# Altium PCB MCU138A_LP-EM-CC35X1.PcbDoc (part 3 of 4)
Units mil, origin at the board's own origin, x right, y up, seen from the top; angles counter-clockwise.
Board outline 2309.44 x 2672.36 mil, 4 copper layers (Top Layer, L02_GND, L03_PWR, Bottom Layer), stack 60 mil thick; 235 components, 167 nets, 678 pads, 887 vias.
Unrouted connection lines stored in the file: 19.
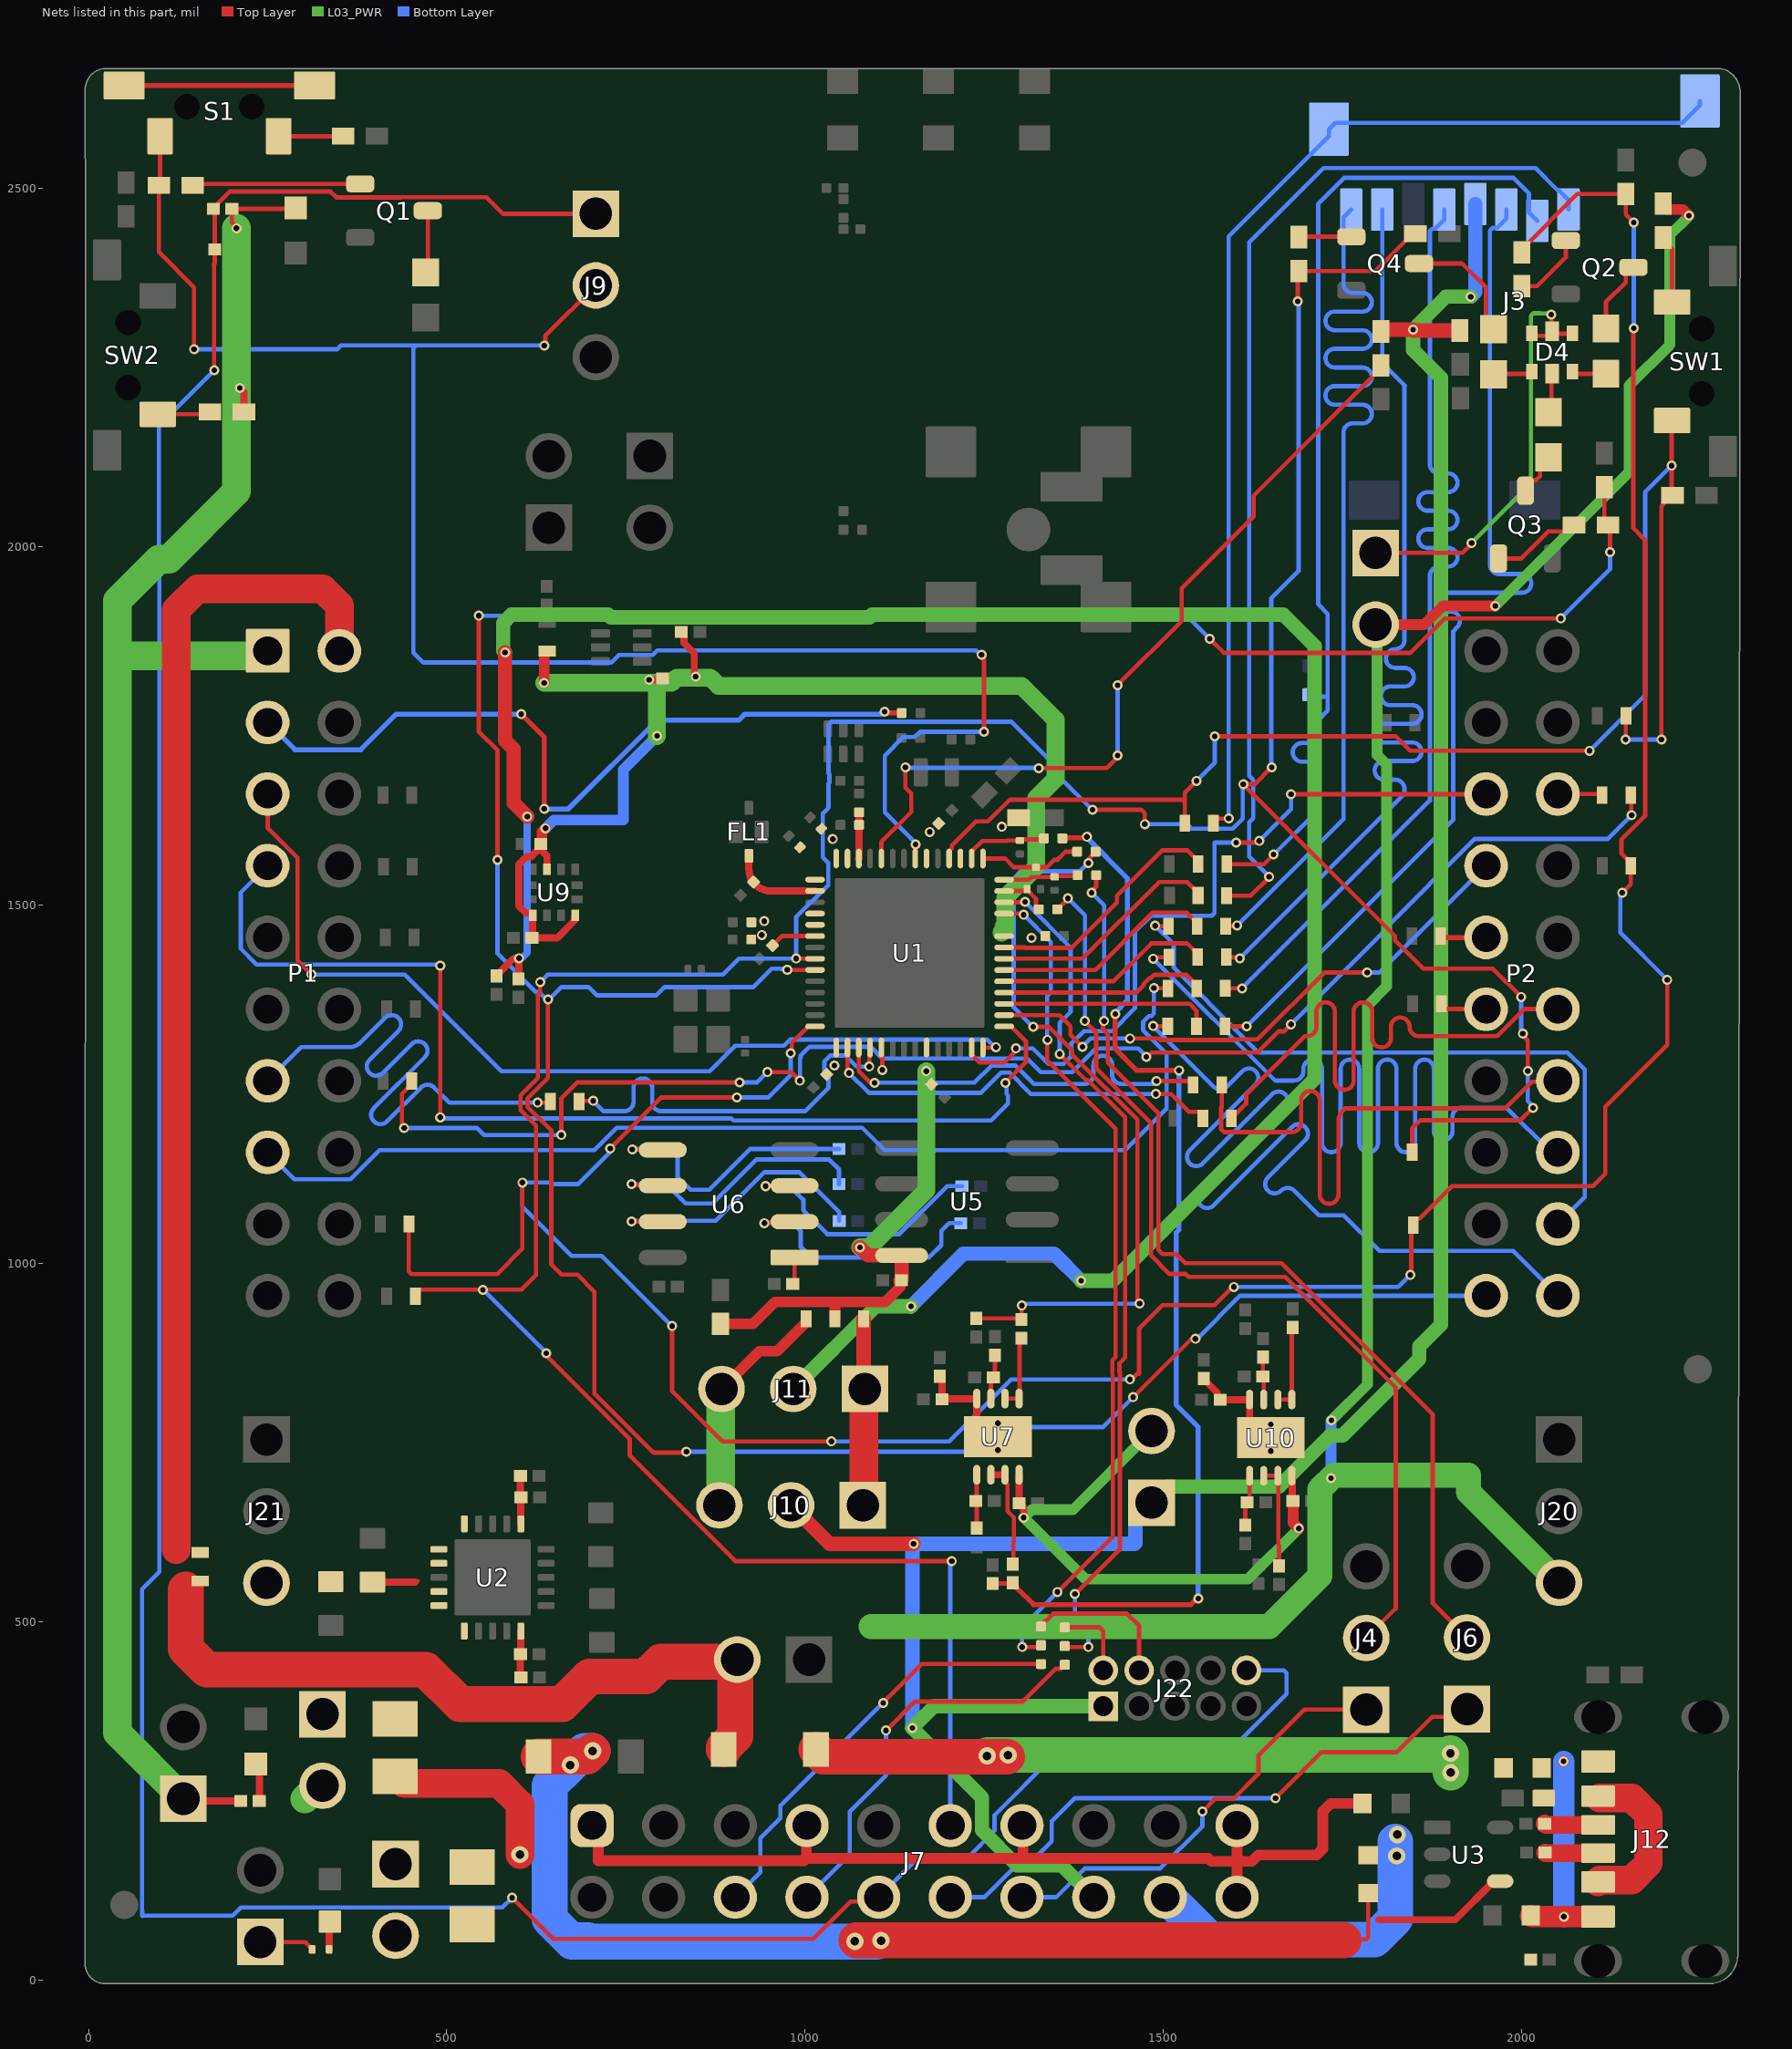
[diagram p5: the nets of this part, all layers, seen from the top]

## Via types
v1: diameter 14, hole 7.87, Top Layer to Bottom Layer, tented both sides, 816 vias
v2: diameter 19.68, hole 7.87, Top Layer to Bottom Layer, tented both sides, 25 vias
v3: diameter 14, hole 8, Top Layer to Bottom Layer, tented both sides, 19 vias
v4: diameter 24, hole 12, Top Layer to Bottom Layer, tented both sides, 14 vias
v5: diameter 19.68, hole 7.87, Top Layer to Bottom Layer, 13 vias

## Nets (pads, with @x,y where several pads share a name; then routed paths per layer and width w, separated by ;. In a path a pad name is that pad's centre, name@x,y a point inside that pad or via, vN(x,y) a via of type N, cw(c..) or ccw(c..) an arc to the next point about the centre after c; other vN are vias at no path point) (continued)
NetD4_1: D4.1 D4.3 D4.5 J19.1 | length 608.6
  Top Layer w6: J19.1@1795.91,1991.39 1916.92,1991.39 1929.83,2004.29 v1(1929.83,2005.24) ; D4.1@2012.62,2294.39 2038.21,2294.39 D4.3@2041.17,2297.34 ; v1(2041.02,2324.1) 2041.17,2323.95 D4.3@2041.17,2297.34 ; D4.5@2069.71,2294.39 2066.76,2297.34 D4.3@2041.17,2297.34
  L03_PWR w6: v1(1929.83,2005.24) 2012.69,2088.1 2012.69,2322.39 2016.21,2325.91 2025.05,2325.91 2025.32,2325.63 2039.49,2325.63 v1(2041.02,2324.1)
NetD4_2: D4.2 R84.2 | length 52.3
  Top Layer w6: R84.2@1960.6,2240.65 1961.19,2241.24 D4.2@2012.62,2241.24
NetD4_4: D4.4 R86.2 | length 52
  Top Layer w6: R86.2@2037.12,2187.93 2041.17,2191.97 D4.4@2041.17,2238.29
NetD4_6: D4.6 R85.2 | length 47.6
  Top Layer w6: D4.6@2069.71,2241.24 2116.87,2241.24 R85.2@2117.21,2241.58
NetD5_1: D5.1 FB3.1 J12.A9 J12.B9 | length 226.3
  Top Layer w40: J12.B9@2106.31,137.01 2108.68,139.39 2152.98,139.39 2176.41,162.82 2176.41,230.88 2152.98,254.31 J12.A9@2108.68,254.31
NetD8_2: D8.2 FB3.2 | length 942.3
  Top Layer w50: D8.2@1015.24,321.96 1025.65,311.55 v4@1281.46,311.55
  L03_PWR w50: v4(1253.88,312.82) 1254.94,313.88 v4(1283.12,313.88) 1283.42,314.18 v4@1898.1,314.18 ; v4(1900.31,316.39) 1900.62,316.08 v4(1900.62,289.57)
NetD9_2: D9.2 R45.1 | length 53.6
  Top Layer w10: D9.2@233.41,301.62 238.37,296.66 R45.1@238.37,250.04
NetD10_2: D10.2 R53.1 | length 39.5
  Top Layer w10: R53.1@335.72,42.82 335.8,42.9 335.8,80.76 D10.2@336.86,81.82
NetFB1_1: FB1.1 J7.18 | length 465.1
  Bottom Layer w50: J7.18@1502.5,115.64 1505.27,115.64 1564.39,56.53 1794.06,56.53 1823.35,85.82 v4@1823.35,193.41
  other v4: 1825.41,173.25 1826.18,202.98
NetFB2_1: FB2.1 J7.1 J7.7 J7.13 J7.19 J7.20 | length 1377.2
  Top Layer w15: J7.1@702.5,215.64 711.29,206.86 711.29,166.46 998.47,166.46 1001.67,169.66 ; J7.7@1002.5,215.64 1001.67,214.82 1001.67,169.66 ; J7.13@1302.5,215.64 1303.99,214.16 1303.99,170.66 ; 1562.5,169.66 1539.77,169.66 1539.63,169.8 1526.38,169.8 1526.24,169.66 1239.77,169.66 1239.63,169.8 1226.38,169.8 1226.24,169.66 1001.67,169.66 ; 1563.21,168.96 1566.52,165.64 1602.5,165.64 ; J7.20@1602.5,115.64 1602.5,165.64 ; J7.19@1602.5,215.64 1602.5,165.64 ; FB2.1@1777.58,246.48 1733.44,246.48 1722.35,235.39 1722.35,183.31 1713.57,174.53 1632.11,174.53 1623.23,165.64 1602.5,165.64
NetFB4_1: FB4.1 J12.A12 J12.B12 R108.2 | length 311.5
  Top Layer w30: FB4.1@2012.22,90.21 2013.77,88.65 v1(2058.52,88.65) 2106.24,88.65 J12.B12@2106.31,88.58
  Bottom Layer w15: v1@2058.15,89.03 v1(2058.52,88.65)
  Bottom Layer w30: v1@2058.15,89.03 v1(2058.15,305.14)
NetJ4_2: J4.2 R96.2 | length 1352.2
  Top Layer w6: R96.2@1351.87,1494.01 1366.69,1508.82 v1(1366.69,1509.37) ; v1(1390.02,1338.25) 1406.09,1322.19 1406.09,1272.09 1482.74,1195.43 1482.74,1010.97 1508.39,985.33 1530.83,985.33 1534.99,981.17 1669.49,981.17 1823.96,826.7 1823.96,518.55 J4.2@1782.8,477.38
  Bottom Layer w6: v1(1366.69,1509.37) 1390.42,1485.64 1390.42,1338.65 v1(1390.02,1338.25)
NetJ6_2: J6.2 R97.2 | length 1374.2
  Top Layer w6: v1(1399.71,1517.26) 1399.71,1519.43 1406.07,1525.78 1406.07,1541.6 R97.2@1406.14,1541.67 ; v1(1417.09,1338.25) 1415.56,1336.72 1415.56,1326.86 1422.07,1320.34 1422.07,1280.41 1492.74,1209.74 1492.74,1018.64 1498.46,1012.93 1517.37,1012.93 1530.09,1000.21 1664.6,1000.21 1875.62,789.18 1875.62,525.8 J6.2@1923.3,478.12
  Bottom Layer w6: v1(1399.71,1517.26) 1399.71,1517.21 1417.09,1499.83 v1(1417.09,1338.25)
NetJ7_6: J7.6 R104.1 | length 599.2
  Top Layer w6: v1(1108.81,386.92) 1162.9,441.02 R104.1@1328.89,441.02
  Bottom Layer w6: J7.6@902.5,115.64 937.28,150.43 937.28,197.93 965.38,226.03 965.38,243.5 v1(1108.81,386.92)
NetJ7_8: J7.8 R105.1 | length 565.8
  Top Layer w6: v1(1112.84,348.26) 1153.24,388.66 1303.76,388.66 1349.64,434.55 1356.97,434.55 1362.24,439.81 R105.1@1362.24,440
  Bottom Layer w6: J7.8@1002.5,115.64 1062.09,175.24 1062.09,235.3 1112.84,286.04 v1(1112.84,348.26)
NetJ12_A5: J12.A5 R48.1 | length 74.1
  Top Layer w25: R48.1@2032.45,177.76 2033.04,177.16 J12.A5@2106.31,177.16
NetJ12_B5: J12.B5 R47.2 | length 75.5
  Top Layer w25: R47.2@2031.62,218.44 2033.52,216.54 J12.B5@2106.31,216.54
NetJ22_2: J22.2 R106.1 | length 110.9
  Top Layer w6: R106.1@1361.99,492.2 1410.87,492.2 1415.87,487.21 J22.2@1415.87,432.24
NetJ22_4: J22.4 R107.1 | length 214.1
  Top Layer w6: R107.1@1328.89,493.48 1328.89,494.26 1345.95,511.32 1449.06,511.32 1465.87,494.51 J22.4@1465.87,432.24
NetQ1_1: Q1.1 R38.2 | length 234.5
  Top Layer w6: R38.2@145.4,2504.22 147.58,2506.39 Q1.1@379.02,2506.39
NetQ1_3: Q1.3 R35.2 | length 87.5
  Top Layer w6: R35.2@470.21,2382.8 473.5,2386.09 Q1.3@473.5,2468.99
NetQ2_1: Q2.1 R87.2 | length 101.8
  Top Layer w6: R87.2@1999.72,2363.68 2021.2,2363.68 2061.21,2403.69 Q2.1@2061.21,2427.43
NetQ2_3: Q2.3 R85.1 | length 102.7
  Top Layer w6: R85.1@2117.21,2304.58 2117.21,2341.18 2144.92,2368.89 2144.92,2381.44 2153.51,2390.03 Q2.3@2155.7,2390.03
NetQ3_1: Q3.1 R88.2 | length 124.5
  Top Layer w6: Q3.1@1967.54,1983.72 1999.22,1983.72 2036.94,2021.43 2063.97,2021.43 R88.2@2072.78,2030.24
NetQ3_3: Q3.3 R86.1 | length 63.8
  Top Layer w6: Q3.3@2004.94,2078.21 2004.94,2084.51 2013.53,2093.1 2019.83,2093.1 2025.32,2098.59 2025.32,2113.14 R86.1@2037.12,2124.94
NetQ4_1: Q4.1 R91.2 | length 73.3
  Top Layer w6: R91.2@1688.91,2432.06 1689.47,2432.61 Q4.1@1761.99,2432.61
NetQ4_3: Q4.3 R84.1 | length 169.9
  Top Layer w6: Q4.3@1856.48,2395.21 1916.53,2395.21 1949.48,2362.27 1949.48,2314.76 R84.1@1960.6,2303.64
NetR8_2: R8.2 SW1.4 | length 95.3
  Top Layer w6: R8.2@2196.85,2431.58 2196.85,2427.65 2209.56,2414.93 SW1.4@2209.56,2341.5
NetR27_2: R27.2 U6.1 | length 37.6
  Top Layer w6: R27.2@982.69,971.7 985.02,974.04 U6.1@985.02,1008.35
NetR36_1: R36.1 S1.3 | length 90.1
  Top Layer w6: S1.3@265.27,2572.79 355.13,2572.79 R36.1@355.29,2572.96
NetR39_1: R39.1 R40.2 U2.16 | length 67.2
  Top Layer w10: R40.2@602.65,703.44 602.65,676 ccw(c605.57,676) R39.1@603.5,673.93 603.25,673.69 U2.16@603.25,636.61
NetR41_1: R41.1 U7.1 U7.2 | length 105.2
  Top Layer w6: U7.2@1278.75,811.42 U7.1@1298.44,811.42 1299.17,812.15 1299.17,893.3 R41.1@1301.51,895.64
NetR41_2: R41.2 R70.2 R95.1 | length 1061.1
  Top Layer w6: R70.2@1238.73,923.25 1299.89,923.25 R41.2@1301.51,921.62 1301.83,921.95 1301.83,940.96 v1(1302.16,941.28) ; v1(1318.07,1330.08) 1339.87,1330.08 1372.74,1297.21 1372.74,1291.29 1463.48,1200.55 1463.48,947.02 v1(1466.64,943.86) ; v1(1394.99,1558.66) 1396.52,1560.19 1396.52,1565.74 R95.1@1405.33,1574.55
  Bottom Layer w6: v1(1302.16,941.28) 1304.73,943.86 v1(1466.64,943.86) ; v1(1318.07,1330.08) 1290.86,1357.29 1290.86,1537.27 1300.79,1547.2 1383.53,1547.2 v1(1394.99,1558.66)
NetR44_1: R44.1 U10.1 U10.2 | length 120.9
  Top Layer w6: U10.2@1659.37,810 U10.1@1679.06,810 ; U10.1@1679.03,810.03 1679.03,909.63 R44.1@1680.17,910.77
NetR49_1: R49.1 R51.2 U2.10 | length 70.9
  Top Layer w10: R51.2@602.28,422.41 ccw(c601.28,423.41) 602.69,423.41 R49.1@602.69,454.64 ccw(c601.33,456) R49.1@603.25,456 ; R49.1@603.25,449.93 U2.10@603.25,487
NetR50_2: R50.2 R68.2 U7.3 | length 62.7
  Top Layer w6: U7.3@1259.07,811.42 1259.07,837.61 1264.71,843.25 R68.2@1264.71,871.82
NetR52_2: R52.2 R69.2 U10.3 | length 59.7
  Top Layer w6: R69.2@1638.56,869.16 1638.56,842.3 R52.2@1638.47,842.21 1639.69,840.99 U10.3@1639.69,810
NetR54_1: R54.1 U1.6 | length 67.3
  Top Layer w6.17: R54.1@952.62,1441.84 967.47,1456.7 U1.6@1013.79,1456.7
NetR56_2: R56.2 U6.6 | length 397.4
  Top Layer w6.17: v1(757.56,1110.58) 758.67,1109.47 800.28,1109.47 U6.6@801.39,1108.35
  Bottom Layer w6.17: v1(757.56,1110.58) 757.73,1110.41 806.27,1110.41 833.02,1083.66 870.39,1083.66 931.74,1145.01 1033.37,1145.01 1047.17,1131.21 R56.2@1047.17,1110.41
NetR57_2: R57.2 U6.5 | length 394.9
  Top Layer w6.17: v1(758.67,1159.19) 759.09,1158.77 800.97,1158.77 U6.5@801.39,1158.35
  Bottom Layer w6.17: v1(758.67,1159.19) 758.99,1159.51 810.7,1159.51 821.82,1148.39 821.82,1120.81 839.91,1102.73 865.98,1102.73 922.77,1159.51 R57.2@1047.17,1159.51
NetR58_2: R58.2 U6.2 | length 381.4
  Top Layer w6.17: v1(943.04,1056.31) 944.06,1057.33 984,1057.33 U6.2@985.02,1058.35
  Bottom Layer w6.17: v1(943.04,1056.31) 982.64,1056.31 993.82,1045.12 993.82,1022.97 1008.45,1008.35 1172.9,1008.35 1190.03,1025.47 1190.03,1045.47 1200.86,1056.31 R58.2@1217.15,1056.31
NetR59_2: R59.2 U6.3 | length 378.9
  Top Layer w6.17: v1(944.65,1107.86) 944.9,1108.11 984.78,1108.11 U6.3@985.02,1108.35
  Bottom Layer w6.17: v1(944.65,1107.86) 978.45,1107.86 997.35,1088.96 997.35,1074.17 1030.71,1040.81 1131.11,1040.81 1198.16,1107.86 R59.2@1218.77,1107.86
NetR60_2: R60.2 U6.7 | length 397.3
  Top Layer w6.17: v1(757.8,1058.67) 757.96,1058.51 801.23,1058.51 U6.7@801.39,1058.35
  Bottom Layer w6.17: v1(757.8,1058.67) 758.57,1059.43 875.25,1059.43 943.29,1127.47 991.77,1127.47 1047.44,1071.8 R60.2@1047.44,1059.43
NetR72_1: R72.1 U7.6 U7.7 | length 150.1
  Top Layer w6: U7.7@1278.75,705.12 1278.75,695.22 1282.29,691.68 1282.29,654.39 1291.01,645.67 1291.01,611.87 1290.37,611.23 1290.37,580.95 R72.1@1289.73,580.31
  Top Layer w10: U7.6@1259.07,705.12 U7.7@1278.75,705.12
NetR72_2: R72.2 R78.2 R98.1 | length 1517.9
  Top Layer w6: R78.2@1261.8,553.32 1288.73,553.32 R72.2@1289.73,554.33
  Top Layer w7: R72.2@1289.73,554.33 1289.73,553.54 1295.39,547.88 1295.39,547.31 1318.62,524.09 1538.23,524.09 1546.46,532.31 v1(1548.35,532.31) ; R98.1@1358.85,1593.09 1359.91,1594.14 1391.91,1594.14 v1(1392.97,1595.2) ; v1(1432.57,1348.21) 1432.57,1299.35 1462.52,1269.41 v1(1521.54,1269.41)
  Bottom Layer w7: v1(1392.97,1595.2) 1392.97,1594.01 1449.4,1537.58 1449.4,1366.93 1432.57,1350.1 v1(1432.57,1348.21) ; v1(1521.54,1269.41) 1521.54,1046.92 1517.4,1042.79 1517.4,802.77 1548.35,771.82 v1(1548.35,532.31)
NetR73_1: R73.1 U10.6 U10.7 | length 146.2
  Top Layer w6: U10.6@1639.69,703.7 U10.7@1659.37,703.7 1660.1,702.98 1660.1,607.54 1660.82,606.82 1661.05,606.6 1661.05,578.19 R73.1@1661.27,577.97
NetR74_2: R74.2 R76.2 U7.5 | length 75.7
  Top Layer w6: R76.2@1239.37,630.66 1239.37,666.82 R74.2@1237.89,668.3 1239.38,669.78 U7.5@1239.38,705.12
NetR75_2: R75.2 R77.2 U10.5 | length 71.2
  Top Layer w6: R77.2@1613.95,634.96 1613.95,664.17 R75.2@1616.54,666.76 1620,670.22 U10.5@1620,703.7
NetR83_2: R83.2 SW2.4 | length 74.3
  Top Layer w6: SW2.4@96.72,2184.8 166.22,2184.8 R83.2@169.63,2188.22
NetS1_1: S1.1 S1.2 | length 265.7
  Top Layer w7: S1.2@49.72,2643.66 S1.1@315.47,2643.66
OP_n: C18.1 R81.2 U10.4 U10.9 | length 201.8
  Top Layer w10: R81.2@1555.93,839.35 1555.93,838.56 1574.95,819.54 1574.95,813.28 1578.22,810.02 C18.1@1579.01,810.02 U10.4@1620,810 1620,767.68 v5(1649.53,738.15) U10.9@1649.53,756.85 v5(1649.53,775.55)
OP_n_1: C17.2 R80.2 U7.4 U7.9 | length 169.4
  Top Layer w10: R80.2@1188.03,842.53 1190.91,839.65 1190.91,814 1191.02,813.89 C17.2@1191.02,810.73 1191.36,811.07 1239.04,811.07 U7.4@1239.38,811.42 U7.9@1239.38,783.81 ; U7.9@1246.22,776.97 v5(1268.91,776.97) U7.9@1268.91,758.27 v5(1268.91,739.57)
P8_GPIO35: J7.11 R21.2 R26.1 R91.1 R93.1 U1.8 | length 5103.3
  Top Layer w6: R26.1@456.16,954.26 456.16,958.76 460.66,963.26 v1@550.38,963.26 ; v1(550.38,963.19) v1@550.38,963.26 ; v1@550.38,964.74 v1@550.38,963.26 ; v1(630.26,1392.44) 630.26,1377.38 627.1,1374.21 627.1,1258.71 602.61,1234.23 602.61,1214.35 624.53,1192.43 624.53,983.55 604.24,963.26 v1@550.38,963.26 ; v1(638.83,874.74) 638.83,871.37 755.22,754.98 755.22,731.81 902.4,584.63 v1(1204.61,584.63) ; v1(987.31,1425.35) 987.45,1425.2 U1.8@1013.79,1425.2 ; v1(1400.75,1633.03) 1469.06,1633.03 1473.77,1628.32 v1(1473.77,1612.97) ; v1(1650.88,1692.35) 1627.17,1668.65 v1(1611.17,1668.61) v1(1611.17,1668.61) 1822.96,1456.82 1822.96,1451.02 1862.57,1411.42 1959.41,1411.42 v1(1999.02,1371.81) ; v1(1687.15,2342.54) 1687.15,2383.05 R91.1@1688.91,2384.81 1795.69,2384.81 1847.51,2436.62 R93.1@1851.45,2436.62 ; R21.2@1846.84,1155.21 1846.84,1188.36 1858.4,1199.92 1998.26,1199.92 v1(2015.47,1217.14) ; v1(2001.21,1320.8) 2001.21,1318.64 2008.24,1311.61 v1(2008.24,1268.38)
  Bottom Layer w6: v1(550.38,963.19) v1(638.83,874.74) ; v1(630.26,1392.44) 640.78,1402.96 885.06,1402.96 907.46,1425.35 v1(987.31,1425.35) 987.31,1483.23 1032.07,1527.99 1032.07,1559.19 1024.54,1566.71 1024.54,1627.89 1032.63,1635.98 1032.63,1669.59 1033.88,1670.84 1033.88,1682.44 1032.63,1683.69 1032.63,1752.29 1036.15,1755.81 1287.95,1755.81 1356.35,1687.41 1356.35,1677.43 v1(1400.75,1633.03) ; J7.11@1202.51,215.65 1202.51,582.53 v1(1204.61,584.63) ; v1(1473.77,1612.97) 1533.24,1612.97 1539.42,1606.79 1596.72,1606.79 1610.6,1620.67 1610.6,1668.04 v1(1611.17,1668.61) ; v1(1650.88,1692.35) 1650.19,1693.03 1650.19,1928.11 1688.33,1966.24 1688.33,2341.36 v1(1687.15,2342.54) ; v1(1999.02,1371.81) 1999.02,1322.99 v1(2001.21,1320.8) ; v1(2008.24,1268.38) 2008.24,1226.54 2015.47,1219.31 v1(2015.47,1217.14)
P9_GPIO34: P2.31 R88.1 R92.1 U1.9 | length 4728.6
  Top Layer w6: v1(544.54,1903.82) 544.54,1742.32 570.72,1716.15 v1(570.72,1563.21) ; v1(641.1,1368.41) 641.1,1258.57 634.53,1252.01 612.61,1230.09 612.61,1218.49 645.78,1185.32 645.78,998.5 659.93,984.34 682.09,984.34 705.88,960.55 705.88,818.51 788.44,735.95 832.85,735.95 v1(834.28,737.38) ; v1(974.97,1409.71) 975.1,1409.58 1013.66,1409.58 U1.9@1013.79,1409.45 ; v1(1457.52,813.35) 1539.22,895.05 1544.19,895.05 v1(1544.46,894.78) ; v1(1564.23,1871.8) 1584.12,1851.9 1844.62,1851.9 1892.65,1899.94 v1(2054.19,1899.94) ; R92.1@2115.15,2083.15 2115.15,2035.11 R88.1@2120.02,2030.24 2122.92,2027.35 v1(2122.92,1992.67)
  Bottom Layer w6: v1(544.54,1903.82) 1532.21,1903.82 v1(1564.23,1871.8) ; v1(570.72,1563.21) 570.72,1432.19 624.46,1378.44 628.91,1378.44 638.93,1368.41 v1(641.1,1368.41) 642.87,1368.41 660.14,1385.69 697.61,1385.69 709.12,1374.18 792.43,1374.18 803.94,1385.69 927.85,1385.69 953.56,1411.4 965.15,1411.4 965.59,1410.96 973.72,1410.96 v1(974.97,1409.71) ; v1(834.28,737.38) 1242.9,737.38 1261.93,756.41 1272.17,756.41 1287.41,771.65 1415.82,771.65 v1(1457.52,813.35) ; v1(1544.46,894.78) 1546.63,894.78 1606.74,954.89 P2.31@1949.99,954.89 ; v1(2054.19,1899.94) 2122.92,1968.67 v1(2122.92,1992.67)
P14_GPIO30: R11.1 R23.1 R24.2 R87.1 R94.1 U1.14 | length 4476.1
  Top Layer w6: R23.1@447.09,1054.98 447.09,988.74 450.61,985.22 570.19,985.22 605.42,1020.46 v1(605.42,1112.86) ; v1(728.12,1160.43) 799.31,1231.62 v1(904.56,1231.62) ; v1(814.24,912.67) 814.24,822.2 884.76,751.68 v1(1036.67,751.68) ; v1(979.64,1293.15) 981.17,1294.68 981.17,1307.94 1003.94,1330.71 U1.14@1013.79,1330.71 ; v1(1453.15,838.12) 1455.31,838.12 1463.21,846.01 1465.74,846.01 1465.74,908.86 1498.57,941.68 1570.86,941.68 1596.35,967.17 v1(1598.26,967.17) ; v1(1844.13,983.82) 1845.66,985.35 1845.66,1050.68 R24.2@1848.54,1053.55 1848.54,1058.05 1853.04,1062.55 1857.54,1062.55 1902.81,1107.83 2099.08,1107.83 2116.2,1124.95 2116.2,1218.47 2202.74,1305.01 v1(2202.74,1395.73) ; R87.1@1999.72,2410.93 1999.72,2414.87 2077.1,2492.25 R94.1@2144.85,2492.25 2144.85,2463.74 v1(2156.21,2452.38) ; v1(2139.93,1517.17) 2152.06,1529.3 R11.1@2152.06,1554.65 2152.06,1559.15 2138.85,1572.36 2138.85,1591.44 2171.93,1624.53 2171.93,2009.44 2155.56,2025.81 2155.56,2304.11 v1(2156.15,2304.69)
  Bottom Layer w6: v1(728.12,1160.43) 728.12,1155.47 683.47,1110.83 646.54,1110.83 644.52,1112.86 v1(605.42,1112.86) 605.42,1079.11 673.94,1010.59 716.26,1010.59 v1(814.24,912.67) v1(814.24,912.67) ; v1(904.56,1231.62) 948.98,1231.62 979.64,1262.28 v1(979.64,1293.15) ; v1(1036.67,751.68) 1200.65,751.68 1287.09,838.12 v1(1453.15,838.12) ; v1(1598.26,967.17) 1827.48,967.17 v1(1844.13,983.82) ; v1(2139.93,1517.17) 2137.14,1514.37 2137.14,1461.33 v1(2202.74,1395.73) ; v1(2156.15,2304.69) 2156.15,2452.31 v1(2156.21,2452.38)
P16_GPIO29: R16.1 R20.1 U1.16 | length 582.4
  Top Layer w6: U1.16@1059.06,1301.19 1059.06,1269.82 1061.02,1267.86 v1(1061.02,1265.69) ; v1(1489.36,1236.4) 1510.41,1236.4 1535.23,1211.58 1550.33,1211.58 1554.73,1207.18 R16.1@1554.73,1202.27
  Bottom Layer w6: v1(1061.02,1265.69) 1088.7,1238.01 1245.51,1238.01 1273.59,1266.1 1285.19,1266.1 1314.89,1236.4 v1(1489.36,1236.4)
P17_GPIO28: R61.1 U1.17 | length 588.1
  Top Layer w6: U1.17@1074.81,1301.19 1074.81,1268.39 1091.46,1251.74 1096.43,1251.74 v1(1096.71,1252.01) ; v1(1490.23,1254.38) 1536.69,1254.38 1541.19,1249.88 R61.1@1541.19,1249.07
  Bottom Layer w6: v1(1096.71,1252.01) 1097.43,1251.3 1098.26,1252.12 1236.09,1252.12 1260.07,1276.1 1293.83,1276.1 1319.41,1250.51 1334.19,1250.51 1389.19,1250.51 ccw(c1389.19,1263.51) 1402.19,1263.51 1402.19,1276.89 cw(c1415.19,1276.89) 1428.19,1276.89 1428.19,1263.51 ccw(c1441.19,1263.51) 1441.19,1250.51 1464.13,1250.51 1486.25,1250.51 1490.12,1254.38 v1(1490.23,1254.38)
P18_GPIO27: R82.2 U1.18 | length 576.4
  Top Layer w6: R82.2@684.5,1225.81 685.57,1226.87 v1(704.1,1226.87) ; v1(1089.47,1274.59) 1089.47,1289.75 1090.56,1290.84 U1.18@1090.56,1301.19 U1.18@1090.92,1300.83
  Bottom Layer w6: v1(704.1,1226.87) 718.57,1212.4 744.48,1212.4 747.48,1212.4 ccw(c747.48,1225.4) 760.48,1225.4 760.48,1245.21 cw(c773.48,1245.21) 786.48,1245.21 786.48,1225.4 ccw(c799.48,1225.4) 799.48,1212.4 878.65,1212.4 999.53,1212.4 1032.64,1245.51 1032.64,1260.75 1026.79,1266.6 1026.79,1281.84 1034.99,1290.04 1056.47,1290.04 1071.92,1274.59 v1(1089.47,1274.59)
P19_GPIO26: R9.1 R17.1 U1.19 | length 2151
  Top Layer w6: v1(440.54,1188.88) 437.46,1191.97 437.46,1236.69 450.89,1250.13 R17.1@450.89,1254.63 ; v1(659.78,1179.23) 659.78,1230.48 682.01,1252.71 v1(908.52,1252.71) ; v1(947.25,1266.98) 980.51,1266.98 v1(992.63,1254.86) ; U1.19@1106.31,1301.19 1106.66,1300.83 1106.66,1286.88 1107.49,1286.05 v1(1107.49,1270.05) v1@1107.97,1270.05 ; v1(1476.09,1288.35) 1477.81,1288.35 1483.6,1294.14 1631.14,1294.14 1660.96,1323.97 1668.54,1323.97 1677.89,1333.32 v1(1677.89,1333.65) ; R9.1@2151.98,1653.58 2152.58,1652.98 2152.58,1626.18 v1(2153.18,1625.58)
  Bottom Layer w6: v1(440.54,1188.88) 542.31,1188.88 551.96,1179.23 v1(659.78,1179.23) ; v1(908.52,1252.71) 932.98,1252.71 v1(947.25,1266.98) ; v1(992.63,1254.86) 992.63,1286.34 993.64,1287.35 993.64,1289.77 1006.22,1302.35 1091.19,1302.35 1107.49,1286.05 ; v1(1107.49,1270.05) 1107.49,1286.05 ; v1(1476.09,1288.35) 1464.55,1299.89 1405.66,1299.89 1372.83,1267.06 1328.7,1267.06 1309.66,1286.1 1107.54,1286.1 1107.49,1286.05 ; v1(1677.89,1333.65) 1806.93,1462.69 1806.93,1464.89 1934.45,1592.41 2120.01,1592.41 v1(2153.18,1625.58)
P31_GPIO15: R28.1 R31.2 U1.31 | length 295.6
  Top Layer w6: U1.31@1277.57,1362.21 1536.55,1362.21 1545.82,1352.95 R31.2@1545.82,1330.85
  Top Layer w10: R28.1@1544.8,1329.83 R31.2@1545.82,1330.85
P32_GPIO14: R19.2 R67.2 U1.32 | length 299.5
  Top Layer w6: U1.32@1277.57,1377.96 1462.38,1377.96 1472.57,1388.15 1472.57,1390.12 1480.77,1398.32 1482.75,1398.32 1487.3,1402.87 1531.8,1402.87 1546.18,1388.49 R67.2@1546.18,1383.99 ; R67.2@1546.18,1383.99 1546.18,1379.49 R67.2@1546.18,1383.99
P33_GPIO13: R22.1 R32.2 U1.33 | length 311.5
  Top Layer w6: U1.33@1277.57,1393.71 1430.07,1393.71 1483,1446.64 1532.74,1446.64 1547.5,1431.88 R32.2@1547.5,1427.38 ; R32.2@1547.5,1427.38 1547.5,1422.88 R32.2@1547.5,1427.38
P34_GPIO12: R25.1 R33.2 U1.34 | length 321.9
  Top Layer w6: U1.34@1277.57,1409.45 1404.83,1409.45 1484.8,1489.42 1532.33,1489.42 1546.91,1474.83 R25.1@1546.91,1470.42 ; R25.1@1546.84,1465.91 R33.2@1546.84,1470.41 R25.1@1546.84,1465.91
P35_GPIO11: R14.2 R29.2 U1.35 | length 334.2
  Top Layer w6: U1.35@1277.57,1425.2 1386.86,1425.2 1493.9,1532.24 1533.21,1532.24 1547.83,1517.62 R29.2@1547.83,1513.12 ; R29.2@1547.83,1513.12 1547.83,1508.62 R29.2@1547.83,1513.12
P36_GPIO10: R30.2 R66.2 U1.36 | length 343.5
  Top Layer w6: U1.36@1277.57,1440.95 1306.35,1440.95 1306.95,1440.35 1371.78,1440.35 1434.78,1503.35 1434.78,1513.28 1497.78,1576.28 1533.57,1576.28 1548.18,1561.67 R30.2@1548.18,1557.17
P41_GPIO6: C15.1 R96.1 U1.41 | length 65.2
  Top Layer w6: U1.41@1277.57,1519.69 C15.1@1307.78,1519.69 ; C15.1@1309.71,1522.27 1309.71,1521.28 1322,1508.99 1322,1497.9 R96.1@1325.89,1494.01
P42_GPIO5: C31.1 R97.1 U1.42 | length 105.2
  Top Layer w6: U1.42@1277.57,1535.44 1312.23,1535.44 1316.18,1539.38 C31.1@1347.92,1539.38 1349.06,1540.53 1379.01,1540.53 R97.1@1380.16,1541.67
P43_GPIO4: C12.1 R95.2 U1.43 | length 145.4
  Top Layer w6: U1.43@1248.04,1564.97 1278.86,1564.97 1291.07,1552.76 C12.1@1322.02,1552.76 1337.01,1552.76 1347.29,1563.04 1351.74,1563.04 1352.3,1563.6 1352.41,1563.6 1363.35,1574.55 R95.2@1379.34,1574.55
P44_GPIO3: C32.1 R98.2 U1.44 | length 118
  Top Layer w6: U1.44@1232.29,1564.97 1232.29,1574.81 1247.05,1589.56 1281.94,1589.56 1282.42,1590.04 C32.1@1299.55,1590.04 1301.07,1591.57 1331.35,1591.57 R98.2@1332.87,1593.09
P46_GPIO2: R34.2 R89.1 R99.1 SW1.3 U1.46 | length 2025.7
  Top Layer w6: U1.46@1200.79,1564.97 1200.79,1575.31 1204.75,1579.27 1204.75,1583.34 1238.06,1616.65 1255.07,1616.65 1285.45,1647.03 1526.15,1647.03 1529.66,1643.52 ; R34.2@1529.66,1614.36 1529.66,1643.52 ; v1(1546.03,1673.36) 1529.66,1656.99 1529.66,1643.52 ; v1(1571.43,1735.48) 1824,1735.48 1844.13,1715.35 v1(2094.53,1715.35) ; v1(2144.75,1730.89) 2145.07,1731.21 R99.1@2145.07,1763.93 ; v1(2194.64,1730.89) 2194.64,2056.23 2197.42,2059.01 2197.42,2062.95 2206.23,2071.76 R89.1@2210.17,2071.76 2208.81,2073.11 v1(2208.81,2113.14) 2208.81,2175.4 SW1.3@2209.56,2176.15
  Bottom Layer w6: v1(1546.03,1673.36) 1571.43,1698.76 v1(1571.43,1735.48) ; v1(2094.53,1715.35) 2171.9,1792.72 2171.9,2076.22 v1(2208.81,2113.14) ; v1(2144.75,1730.89) v1(2194.64,1730.89)
P52_GPIO37: R2.2 R4.1 U1.52 | length 1149.8
  Top Layer w6: U1.52@1106.31,1564.97 1106.31,1588.14 1148.01,1629.85 1148.01,1655.88 1139.83,1664.06 v1(1139.83,1692.25) ; v1(1325.94,1691.09) 1420.71,1691.09 1435.78,1706.16 v1(1435.78,1708.67) ; v1(1435.78,1806.84) 1525.15,1896.2 1525.15,1941.67 1625.81,2042.33 1625.81,2071.38 1803.52,2249.1 R4.1@1803.52,2253.03
  Bottom Layer w6: v1(1139.83,1692.25) 1140.41,1691.67 1325.36,1691.67 v1(1325.94,1691.09) ; v1(1435.78,1708.67) v1(1435.78,1806.84)
PA_LDO_OUT: C29.2 U1.1
RESET: J9.2 R38.1 S1.4 U1.49 | length 2583.2
  Top Layer w6: S1.4@99.92,2572.79 99.92,2505.98 R38.1@98.16,2504.22 98.16,2411.17 147.36,2361.97 v1(147.36,2275.57) ; v1(635.9,2280.88) 637.43,2282.42 637.43,2294.11 J9.2@707.96,2364.64 ; U1.49@1153.55,1564.97 1153.55,1584.4 v1(1153.93,1584.79) ; v1(1246.06,1849.16) 1249.6,1845.63 v1(1249.6,1741.81)
  Bottom Layer w6: v1(147.36,2275.57) 346.85,2275.57 352.17,2280.88 456.86,2280.88 ; v1(635.9,2280.88) 456.86,2280.88 ; v1(1153.93,1584.79) 1153.93,1586.95 1111.05,1629.84 1111.05,1708.61 1136.85,1734.42 1152.59,1734.42 1159.99,1741.81 v1(1249.6,1741.81) ; v1(1246.06,1849.16) 1244.64,1849.16 1238.54,1855.26 793.69,1855.26 787.59,1849.16 739.95,1849.16 729.26,1838.47 467.36,1838.47 453.34,1852.49 453.34,2277.37 456.86,2280.88
RF_A: C11.2 C30.2 U1.54 | length 64.8
  Top Layer w10.25: U1.54@1074.81,1564.97 1074.98,1565.13 1074.98,1611.82 C30.2@1075.14,1611.99 C11.2@1075.15,1629.6
RF_BG: C28.2 FL1.1 U1.2 | length 129.8
  Top Layer w10.25: FL1.1@921.34,1570.33 921.34,1550.69 ccw(c952.34,1550.69) 952.34,1519.69 U1.2@1013.79,1519.69
SDMMC_CD: J3.9 R34.1 | length 1582.4
  Top Layer w6: R34.1@1569.66,1614.36 1569.66,1616.29 1574.16,1620.79 v1(1590.92,1620.79)
  Bottom Layer w6: v1(1590.92,1620.79) 1590.92,2433.04 1730.72,2572.84 J3.9@1730.72,2582.68 1739.54,2591.51 2223.87,2591.51 2248.43,2616.07 J3.9@2248.43,2622.05
SDMMC_CLK: J3.5 R67.1 | length 1458.7
  Top Layer w6: R67.1@1586.18,1383.99 1609.2,1383.99 v1(1609.45,1383.75)
  Bottom Layer w6: v1(1609.45,1383.75) 1871.59,1645.89 1871.59,1930.31 1871.59,1959.31 cw(c1884.59,1959.31) 1884.59,1972.31 1897.18,1972.31 ccw(c1897.18,1985.31) 1897.18,1998.31 1868.37,1998.31 cw(c1868.37,2011.31) 1868.37,2024.31 1897.18,2024.31 ccw(c1897.18,2037.31) 1897.18,2050.31 1868.37,2050.31 cw(c1868.37,2063.31) 1868.37,2076.31 1897.18,2076.31 ccw(c1897.18,2089.31) 1897.18,2102.31 1884.59,2102.31 cw(c1884.59,2115.31) 1871.59,2115.31 1871.59,2151.58 1871.59,2440.43 1875.1,2443.95 1878.99,2443.95 1891.74,2456.7 J3.5@1891.74,2470.48
SDMMC_CMD: J3.3 R31.1 | length 1493.4
  Top Layer w6: R31.1@1585.82,1330.85 1615.77,1330.85 v1(1615.82,1330.8)
  Bottom Layer w6: v1(1615.82,1330.8) 1904.17,1619.16 1904.17,1880.88 1904.17,1882.23 1909.64,1887.69 ccw(c1900.44,1896.88) 1900.44,1909.88 1894.59,1909.88 cw(c1894.59,1922.88) 1894.59,1935.88 2000.13,1935.88 ccw(c2000.13,1948.88) 2000.13,1961.88 1968.46,1961.88 cw(c1968.46,1974.88) 1955.46,1974.88 1955.46,2040.14 1955.46,2441.44 1958.97,2444.96 1965.61,2444.96 1978.35,2457.71 J3.3@1978.35,2470.48
SDMMC_D0: J3.7 R32.1 | length 1488.7
  Top Layer w6: R32.1@1587.5,1427.38 1604.83,1427.38 v1(1606.45,1425.76)
  Bottom Layer w6: v1(1606.45,1425.76) 1836.14,1655.44 1836.14,1659.01 1836.14,1662.01 ccw(c1823.14,1662.01) 1823.14,1675.01 1807.48,1675.01 cw(c1807.48,1688.01) 1807.48,1701.01 1846.95,1701.01 ccw(c1846.95,1714.01) 1846.95,1727.01 1807.48,1727.01 cw(c1807.48,1740.01) 1807.48,1753.01 1846.95,1753.01 ccw(c1846.95,1766.01) 1846.95,1779.01 1816.26,1779.01 cw(c1816.26,1792.01) 1816.26,1805.01 1836.14,1805.01 ccw(c1836.14,1818.01) 1836.14,1831.01 1823.14,1831.01 cw(c1823.14,1844.01) 1823.14,1857.01 ccw(c1823.14,1870.01) 1836.14,1870.01 1836.14,1967.32 1836.14,2224.28 ; 1805.12,2255.3 J3.7@1805.12,2470.48 ; 1805.85,2255.42 1836.86,2224.41
SDMMC_D1: J3.8 R33.1 | length 1459.5
  Top Layer w6: R33.1@1586.84,1470.41 1601.41,1470.41 v1(1602.74,1471.74)
  Bottom Layer w6: v1(1602.74,1471.74) 1750.96,1619.96 1750.96,2130.18 1750.96,2159.18 cw(c1763.96,2159.18) 1763.96,2172.18 1777.59,2172.18 ccw(c1777.59,2185.18) 1777.59,2198.18 1738.85,2198.18 cw(c1738.85,2211.18) 1738.85,2224.18 1777.59,2224.18 ccw(c1777.59,2237.18) 1777.59,2250.18 1738.85,2250.18 cw(c1738.85,2263.18) 1738.85,2276.18 1777.59,2276.18 ccw(c1777.59,2289.18) 1777.59,2302.18 1738.85,2302.18 cw(c1738.85,2315.18) 1738.85,2328.18 1777.59,2328.18 ccw(c1777.59,2341.18) 1777.59,2354.18 1763.96,2354.18 cw(c1763.96,2367.18) 1750.96,2367.18 1750.96,2395.98 1750.96,2459.62 J3.8@1761.82,2470.48
SDMMC_D2: J3.1 R29.1 | length 1492.9
  Top Layer w6: R29.1@1587.83,1513.12 1621.62,1513.12 1647.31,1538.81 v1(1647.31,1539.68)
  Bottom Layer w6: v1(1647.31,1539.68) 1619.44,1567.55 1619.44,1615.37 1625.17,1621.1 1625.17,1674.41 1619.44,1680.14 1619.44,2424.84 1723.02,2528.42 2018.92,2528.42 2050.33,2497 2052.22,2497 2064.97,2484.26 J3.1@2064.97,2470.48
SDMMC_D3: J3.2 R30.1 R65.2 | length 1452.2
  Top Layer w6: R30.1@1588.18,1557.17 1640.11,1557.17 v1(1653.62,1570.68)
  Bottom Layer w6: v1(1653.62,1570.68) 1715.85,1632.91 1715.85,1684.16 1715.85,1687.16 ccw(c1702.85,1687.16) 1702.85,1700.16 1693.23,1700.16 cw(c1693.23,1713.16) 1693.23,1726.16 1702.85,1726.16 ccw(c1702.85,1739.16) 1715.85,1739.16 1715.85,1758.24 1728.9,1771.29 1728.9,1776.45 1728.9,1790.95 ; R65.2@1703.53,1793.51 1706.1,1790.95 1728.9,1790.95 ; J3.2@2021.66,2454.73 2009.64,2466.75 2009.64,2493.26 1988.02,2514.88 1752.15,2514.88 1715.85,2478.58 1715.85,1919.56 1728.9,1906.51 1728.9,1790.95
SLOW_CLK_IN: P1.2 R5.2 | length 1091.2
  Top Layer w7: v1(603.77,1766.38) 635.93,1734.21 v1(635.93,1634.13) ; v1(1110.61,1769.81) 1112.3,1768.12 R5.2@1134.66,1768.12
  Bottom Layer w7: P1.2@249.99,1754.89 288,1716.88 379.93,1716.88 429.42,1766.38 v1(603.77,1766.38) ; v1(635.93,1634.13) 669.57,1634.13 793.2,1757.76 907.04,1757.76 915.59,1766.31 1105.22,1766.31 1108.72,1769.81 v1(1110.61,1769.81)
SPI0_CLK: P1.7 R82.1 | length 836.9
  Top Layer w6: v1(626.61,1224.29) 642.99,1224.29 R82.1@644.5,1225.81
  Bottom Layer w6: P1.7@249.99,1254.89 296.85,1301.76 359.61,1301.76 363.85,1301.76 ccw(c363.85,1323.95) 379.52,1308.23 414.04,1342.75 cw(c423.23,1333.56) 432.42,1342.75 cw(c423.23,1333.56) 432.42,1324.36 392.19,1284.13 ccw(c401.38,1274.94) 392.19,1265.74 ccw(c401.38,1274.94) 410.57,1265.74 450.8,1305.98 cw(c460,1296.79) 469.19,1305.98 cw(c460,1296.79) 469.19,1287.59 398.18,1216.58 ccw(c407.37,1207.39) 398.18,1198.2 ccw(c407.37,1207.39) 416.56,1198.2 463.85,1245.49 cw(c473.04,1236.29) 482.24,1245.49 503.44,1224.29 540.48,1224.29 v1(626.61,1224.29) v1@626,1224.9
SPI0_CS: P2.18 R9.2 | length 62.5
  Top Layer w6: P2.18@2049.99,1654.89 2110.66,1654.89 R9.2@2111.98,1653.58
SPI0_PICO: P2.15 R16.2 | length 880.6
  Top Layer w6: R16.2@1594.73,1202.27 1615.2,1222.74 1615.2,1235.11 1697.22,1317.13 1700.22,1317.13 ccw(c1700.22,1330.13) 1713.22,1330.13 1713.22,1351.29 cw(c1726.22,1351.29) 1739.22,1351.29 1739.22,1255.27 ccw(c1752.22,1255.27) 1765.22,1255.27 1765.22,1351.29 cw(c1778.22,1351.29) 1791.22,1351.29 1791.22,1314.4 ccw(c1804.22,1314.4) 1817.22,1314.4 1817.22,1330.13 cw(c1830.22,1330.13) 1843.22,1330.13 ccw(c1856.22,1330.13) 1856.22,1317.13 1905.07,1317.13 1965.27,1317.13 2003.04,1354.89 P2.15@2049.99,1354.89
SPI0_POCI: P2.14 R61.2 | length 865.5
  Top Layer w6: R61.2@1581.19,1249.07 1581.19,1218.13 1580.23,1217.17 1580.23,1187.37 1584.33,1183.27 1646.47,1183.27 1678.96,1183.27 ccw(c1678.96,1196.27) 1691.96,1196.27 1691.96,1227.62 cw(c1704.96,1227.62) 1717.96,1227.62 1717.96,1096.27 ccw(c1730.96,1096.27) 1743.96,1096.27 1743.96,1197.67 cw(c1766.15,1197.67) 1750.46,1213.37 1753.46,1216.37 1976.86,1216.37 2013.99,1253.5 2048.59,1253.5 P2.14@2049.99,1254.89
  Bottom Layer w6: P2.14@2049.99,1252.23 P2.14@2049.99,1254.89
SPI1_CLK: P1.8 R19.1 | length 1546.6
  Top Layer w6: v1(1486.57,1384.32) 1487.02,1383.87 R19.1@1506.25,1383.87
  Bottom Layer w6: P1.8@249.99,1154.89 287.5,1117.38 365.52,1117.38 406.28,1158.14 706.03,1158.14 737.2,1189.31 1079.62,1189.31 1110.79,1158.14 1446.52,1158.14 1504.23,1215.85 1504.23,1292.56 1471.41,1325.38 1471.41,1336.98 1479.61,1345.18 1483.06,1345.18 1486.57,1348.69 v1(1486.57,1384.32)
SPI1_CS: P2.12 R25.2 | length 951.5
  Top Layer w6: v1(1488.35,1471.21) 1489.14,1470.42 R25.2@1506.91,1470.42
  Bottom Layer w6: v1(1488.35,1471.21) 1514.2,1445.36 1514.2,1412.62 1610.02,1316.8 1632.39,1294.43 2063.5,1294.43 2087.5,1270.43 2087.5,1092.41 P2.12@2049.99,1054.89
SPI1_PICO: P2.13 R22.2 | length 1546.6
  Top Layer w6: v1(1485.5,1425.22) 1487.58,1427.31 R22.2@1507.5,1427.31
  Bottom Layer w6: v1(1485.5,1425.22) 1655.58,1255.14 1655.67,1255.14 1679.08,1255.14 1682.08,1255.14 ccw(c1682.08,1268.14) 1695.08,1268.14 1695.08,1271.43 cw(c1708.08,1271.43) 1721.08,1271.43 1721.08,1168.22 ccw(c1734.08,1168.22) 1747.08,1168.22 1747.08,1271.43 cw(c1760.08,1271.43) 1773.08,1271.43 1773.08,1168.14 ccw(c1786.08,1168.14) 1799.08,1168.14 1799.08,1271.43 cw(c1812.08,1271.43) 1825.08,1271.43 1825.08,1168.14 ccw(c1838.08,1168.14) 1851.08,1168.14 1851.08,1271.43 cw(c1864.08,1271.43) 1877.08,1271.43 1877.08,1184.64 ccw(c1890.08,1184.64) 1903.08,1184.64 1903.08,1204.38 cw(c1916.08,1204.38) 1916.08,1217.38 1964.61,1217.38 1978.49,1217.38 2040.97,1154.89 P2.13@2049.99,1154.89
SPI1_POCI: P2.11 R28.2 | length 1546.6
  Top Layer w6: v1(1485.41,1331.18) 1485.78,1330.81 R28.2@1505.98,1330.81
  Bottom Layer w6: v1(1485.41,1331.18) 1567.87,1248.72 1569.99,1246.6 ccw(c1579.19,1255.79) 1588.38,1246.6 1609.99,1268.2 cw(c1619.18,1259.01) 1628.37,1268.2 cw(c1619.18,1259.01) 1628.37,1249.82 1536.43,1157.88 ccw(c1545.62,1148.68) 1536.43,1139.49 ccw(c1545.62,1148.68) 1554.81,1139.49 1651.27,1235.95 cw(c1660.46,1226.76) 1669.65,1235.95 cw(c1660.46,1226.76) 1669.65,1217.57 1551.6,1099.51 ccw(c1560.79,1090.32) 1551.6,1081.12 ccw(c1560.79,1090.32) 1569.98,1081.12 1679.22,1190.36 cw(c1688.41,1181.17) 1697.6,1190.36 cw(c1688.41,1181.17) 1697.6,1171.97 1645.58,1119.95 ccw(c1654.77,1110.76) 1645.58,1101.57 ccw(c1654.77,1110.76) 1663.96,1101.57 cw(c1673.16,1092.37) 1682.35,1101.57 1716.8,1067.12 1751.35,1067.12 1801.09,1017.38 1824.95,1017.38 1987.5,1017.38 P2.11@2049.99,954.89
SWCLK: R104.2 R107.2 U1.39 | length 1189.5
  Top Layer w6: U1.39@1277.57,1488.19 1302.89,1488.19 1304.63,1486.45 v1(1304.86,1486.45) ; v1(1302.7,464.76) 1326.16,464.76 R107.2@1328.89,467.49 ; v1(1338.19,1311.97) 1337.54,1311.31 1337.54,1283.7 1432.94,1188.3 1432.94,869.25 1428.53,864.84 1428.53,844.96 1429.15,844.33 1429.15,618.78 v1(1351.98,541.61)
  Bottom Layer w6: v1(1302.7,464.76) 1302.56,464.9 1302.56,492.18 v1(1351.98,541.61) ; v1(1304.86,1486.45) 1342.76,1448.55 1342.76,1378.33 1337.54,1373.11 1337.54,1312.62 v1(1338.19,1311.97)
SWDIO: R105.2 R106.2 U1.40 | length 1211.7
  Top Layer w6: U1.40@1277.57,1503.94 1305.94,1503.94 v1(1306.55,1504.55) ; v1(1355.02,1292.27) 1391.51,1255.78 1394.11,1255.78 1446.26,1203.64 1446.26,868.42 1438.53,860.7 1438.53,849.1 1439.15,848.48 1439.15,601.34 v1(1376.39,538.59) ; R105.2@1362.24,465.98 1363.47,464.76 v1(1395.1,464.76)
  Bottom Layer w6: v1(1306.55,1504.55) 1370.35,1440.75 1370.35,1350.9 1355.02,1335.57 v1(1355.02,1292.27) ; v1(1376.39,538.59) 1376.39,504.48 1395.1,485.77 v1(1395.1,464.76)
UART0_CTS: P2.38 U1.27 | length 1053.1
  Top Layer w6: U1.27@1232.29,1301.19 1232.29,1291.34 1243.23,1280.41 1278.11,1280.41 1293.95,1296.24 v1(1293.95,1300.1) ; v1(1601.17,1587.2) 1630.41,1587.2 1632.69,1589.48 v1(1633.44,1589.48) ; v1(1677.86,1654.63) 1677.99,1654.76 1949.86,1654.76 P2.38@1949.99,1654.89
  Bottom Layer w6: v1@1293.95,1297.5 v1(1293.95,1300.1) 1317.55,1300.1 1339.38,1278.27 1360.82,1278.27 1370.88,1288.33 1370.88,1306.3 1388.84,1324.25 1428.42,1324.25 1460.05,1355.89 1460.05,1462.71 1482.55,1485.21 1567.5,1485.21 1571.01,1488.72 1571.01,1587.2 v1(1601.17,1587.2) ; v1(1633.44,1589.48) 1677.86,1633.91 v1(1677.86,1654.63)
UART0_RTS: P2.37 U1.30 | length 803.6
  Top Layer w6: U1.30@1277.57,1346.46 1354.78,1346.46 1370,1331.25 1370,1319.1 v1(1386.74,1302.36) ; v1(1453.36,1313.91) 1493.48,1313.91 1495.58,1311.81 1596.18,1311.81 1597.07,1312.7 1631.05,1312.7 1724.23,1405.88 v1(1784.13,1405.88)
  Bottom Layer w6: v1(1386.74,1302.36) 1398.29,1313.91 v1@1452.8,1313.91 ; v1(1784.13,1405.88) 1800.97,1405.88 P2.37@1949.99,1554.89
UART0_RX: P1.3 U1.28 | length 1329.1
  Top Layer w6: P1.3@249.99,1654.89 249.99,1607.94 291.75,1566.18 291.75,1422.69 v1(311.29,1403.15) ; U1.28@1248.04,1301.19 1265.66,1301.19 v1(1266.26,1301.78)
  Bottom Layer w6: v1(311.29,1403.15) 440.96,1403.15 575.9,1268.21 866.67,1268.21 902.38,1303.92 970.61,1303.92 979.04,1312.35 1254.2,1312.35 1264.77,1301.78 v1(1266.26,1301.78)
UART0_TX: P1.4 U1.29 | length 1574.5
  Top Layer w6: v1(490.82,1203.9) v1(490.82,1415.65) ; U1.29@1277.57,1330.71 1287.41,1330.71 1307.95,1310.17 1307.95,1280.66 v1(1279.39,1252.1)
  Bottom Layer w6: P1.4@249.99,1554.89 212.47,1517.38 212.47,1439.36 234.69,1417.15 489.33,1417.15 v1(490.82,1415.65) ; v1(490.82,1203.9) 492.32,1202.4 896.76,1202.4 899.85,1199.31 1259.6,1199.31 1283.01,1222.72 1283.01,1234.32 1280.92,1236.4 1280.92,1250.57 v1(1279.39,1252.1)
UART1_RX: P2.35 R18.1 | length 67.3
  Top Layer w6: R18.1@1887.6,1362.41 1887.6,1359.39 1892.1,1354.89 P2.35@1949.99,1354.89
UART1_RX_XDS: J4.1 J7.14 | length 615.8
  Top Layer w6: v1(1554.25,235.31) 1571.71,252.76 1597.49,252.76 1632.43,287.7 1632.43,313.49 1696.33,377.38 J4.1@1782.8,377.38
  Bottom Layer w6: J7.14@1302.5,115.64 1350.01,115.64 1390.18,155.82 1495.17,155.82 1554.25,214.9 v1(1554.25,235.31)
UART1_TX: P2.36 R13.1 | length 64.2
  Top Layer w7: R13.1@1886.57,1456.82 1888.49,1454.89 P2.36@1949.99,1454.89
UART1_TX_XDS: J6.1 J7.12 | length 846
  Top Layer w6: v1(1656.21,253.86) 1720.46,318.11 1825.56,318.11 1874.88,367.43 1912.61,367.43 J6.1@1923.3,378.12
  Bottom Layer w6: J7.12@1202.5,115.64 1250.01,115.64 1294.24,159.88 1310.27,159.88 1344.13,193.73 1344.13,221.86 1376.13,253.86 v1(1656.21,253.86)
VBAT_CC_1V8: C22.1 C24.1 C25.1 C27.1 J16.1 R63.2 U1.4 U1.5 U1.45 U1.48
  other v3: 939.37,1458.36 942.82,1477.57 1173.85,1602.12 1274.42,1609.22
VCC_BRD_1V8: J10.3 J11.3 J14.1 J16.2 R43.1 R53.2 R63.1 | length 402.1
  Top Layer w6: J14.1@239.78,53.23 302.68,53.23 312.1,43.81 R53.2@312.1,42.82
  Top Layer w15: J11.3@883.3,824.84 935.96,877.5 960.73,877.5 1001.5,918.26 R43.1@1001.5,922.76
  L03_PWR w40: J10.3@880.36,662.51 881.83,663.98 881.83,823.37 J11.3@883.3,824.84
VCC_BRD_3V3: D2.2 J10.1 J11.1 J13.1 J17.2 J19.2 J20.3 P1.1 R8.1 R37.2 R42.2 R45.2 R64.1 R83.1 | length 6621.4
  Top Layer w6: v1(206.51,2444.43) 206.51,2446.6 200.2,2452.9 R37.2@200.2,2471.58 288.01,2471.58 D2.2@289.27,2472.84
  Top Layer w10: J13.1@132.3,253.09 135.36,250.04 R45.2@212.39,250.04 ; v1(211.02,2221.35) 216.87,2215.5 R83.1@216.87,2188.22 ; J11.1@1081.5,826.64 J11.1@1083.3,824.84
  Top Layer w15: J19.2@1795.91,1891.39 1863.59,1891.39 1889.63,1917.42 v1(1962.92,1917.42) ; R8.1@2196.85,2478.83 2196.85,2474.89 2201.16,2470.58 2224.47,2470.58 v1(2233.13,2461.92)
  Top Layer w20: J11.1@1081.5,826.64 R42.2@1081.5,922.76
  Top Layer w35: J20.3@2046.07,560.22 J20.3@2051.8,554.48
  Top Layer w40: R64.1@428.1,284.37 430.71,284.37 440.66,274.42 573.02,274.42 601.91,245.53 v4(601.91,175.23) ; J10.1@1080.36,662.51 1081.83,663.98 1081.83,823.37 J11.1@1083.3,824.84
  L03_PWR w15: v1(1734.43,781.27) 1784.58,831.42 1784.58,1359.87 1811.17,1386.46 1811.17,1696.16 1797.88,1709.45 1797.88,1889.41 J19.2@1795.91,1891.39 ; v1(1962.92,1917.42) 2149.6,2104.1 2149.6,2224.89 2206.5,2281.79 2206.5,2435.29 v1(2233.13,2461.92)
  L03_PWR w35: 1091.98,493.26 1647.5,493.26 1718.09,563.85 1718.09,685.05 1737.69,704.65 1925.39,704.65 1925.39,680.89 J20.3@2051.8,554.48
  L03_PWR w40: J13.1@132.3,253.09 40.42,344.98 40.42,1847.66 ; v1(206.51,2444.43) 206.51,2077.12 112.18,1982.79 98.46,1982.79 40.42,1924.75 40.42,1847.66 ; P1.1@249.99,1854.89 242.75,1847.66 40.42,1847.66 ; J17.2@301.73,253.09 319.75,271.11 J17.2@326.5,271.11
  Bottom Layer w15: v1(1733.58,700.54) 1733.58,780.42 v1(1734.43,781.27)
VCC_BRD_5V: C2.2 C3.2 D8.1 J5.2 J21.3 R46.1 U2.1 U2.2 U2.4 U2.5 U2.6 U2.20 | length 1104.6
  Top Layer w6.17: 455.36,555.13 ccw(c455.36,561.06) 459.55,556.87
  Top Layer w10: C3.2@394.1,555.68 394.65,555.13 455.36,555.13
  Top Layer w50: 135.72,544.78 135.72,462.53 165.01,433.24 470.4,433.24 518.37,385.27 661.06,385.27 699.33,423.54 777.59,423.54 798.34,444.3 J5.2@902.39,444.3 ; D8.1@886.3,321.96 886.3,324.16 902.39,340.25 J5.2@902.39,444.3 ; J5.2@905.26,447.16 J5.2@902.39,444.3
VCC_LP_5V: P1.21 R46.2 | length 1625.3
  Top Layer w40: 122.46,600.99 122.46,1267.01 ; 122.58,1265.42 122.58,1617.79 122.46,1617.67 122.46,1911.78 152.1,1941.42 326.56,1941.42 349.99,1917.99 P1.21@349.99,1854.89
VCC_OPAMP: C13.2 C14.2 J8.2 U7.8 U10.8 | length 814.1
  Top Layer w6: U10.8@1679.06,703.7 U10.8@1679.52,703.24
  Top Layer w10: U7.8@1298.44,705.12 1298.44,665.65 1299.04,665.65 1304.4,660.29 1304.4,657.39 1305.01,656.78 v1(1305.01,645.29) ; C14.2@1679.52,671.61 U10.8@1679.52,703.24
  Top Layer w15: C14.2@1680.49,668.7 1680.94,668.25 1680.94,637.93 v1(1688.68,630.18)
  L03_PWR w15: J8.2@1483.3,766.19 1373.55,656.43 1316.15,656.43 v1(1305.01,645.29) 1390.97,559.33 1617.82,559.33 v1(1688.68,630.18)
VDD_PA: C26.2 J17.1 R64.2 U1.55 U1.56
  other v3: 1038.54,1592.11
VDD_SF_IN: C33.1 C40.1 R42.1 R43.2 R55.2 U1.23 U5.8 | length 696.5
  Top Layer w10: C40.1@1132.65,975.51 1133.42,976.28 C40.1@1134.21,976.28
  Top Layer w15: R55.2@881.8,915.7 927.47,915.7 958.04,946.26 1041.5,946.26 ; R42.1@1041.5,922.76 1041.5,946.26 ; C40.1@1132.65,975.51 1132.65,967.13 1111.79,946.26 1041.5,946.26
  Top Layer w20: v1(1076.55,1022.43) 1087.71,1011.27 1134.24,1011.27 U5.8@1134.49,1011.02 1134.49,977.35 C40.1@1132.65,975.51
  L03_PWR w25: v1(1076.55,1022.43) 1089.31,1022.43 1168.9,1102.02 v3(1168.9,1268.35)
VIO1_IN: C16.1 C34.1 C42.1 J3.4 J7.16 J8.1 J10.2 J22.1 R1.1 R2.1 R62.2 R100.2 R101.2 U1.37 U9.3 U9.7 U9.10 | length 5582.1
  Top Layer w10: 632.03,1576.34 639.66,1568.71 U9.3@639.66,1550.01 ; C16.1@632.03,1577.1 632.03,1585.22 630.46,1585.22 627.19,1581.95 627.19,1577.1 623.32,1573.22 617.61,1567.52 611.17,1567.52 600.34,1556.7 600.34,1498.85 610.28,1488.91 619.46,1488.91 619.97,1488.4 U9.7@619.97,1485.84 619.46,1485.33 619.46,1454.76 C42.1@618.82,1454.12 653.93,1454.12 678.52,1478.7 678.52,1485.33 U9.10@679.03,1485.84 ; v1(782.26,1814.36) 799.28,1814.36 R101.2@801.09,1816.17 ; R100.2@827.02,1881.11 827.81,1881.11 831.08,1877.84 831.08,1865.7 845.13,1851.65 845.13,1820.91 v1(847.13,1818.91)
  Top Layer w15: C16.1@632.03,1585.22 632.8,1585.99 632.8,1602.35 v1(637.72,1607.27) ; v1(635.84,1810.07) 635.84,1854.56 R62.2@640.12,1854.56
  Top Layer w20: J10.2@980.36,662.51 1034.02,608.84 v1(1151.24,608.84) ; R2.1@1803.11,2300.35 1803.11,2301.13 1804.92,2302.94 v1(1848.05,2302.94) 1849.22,2301.77 R1.1@1913.09,2301.77
  L03_PWR w20: J7.16@1402.5,115.64 1357.79,160.36 1295.4,160.36 1246.62,209.13 1246.62,254.67 v1(1149.61,351.68) 1180.16,382.24 J22.1@1415.87,382.24 ; J8.1@1483.3,666.19 1505.78,688.67 1661.17,688.67 1732.28,759.77 1749.91,759.77 1856.87,866.74 1856.87,884.37 1886.87,914.37 1886.87,2235.86 1848.05,2274.67 v1(1848.05,2302.94) 1894.02,2348.91 v1(1928.59,2348.91)
  L03_PWR w25: v1(635.84,1810.07) 793.13,1810.07 ; v1(793.13,1735.92) 793.13,1810.07 ; 1274.08,1461.85 1278.88,1466.65 1278.88,1510.12 1322.55,1553.79 1322.55,1649.4 1349.44,1676.28 1349.44,1758.38 1301.94,1805.87 879.15,1805.87 867.67,1817.34 820.79,1817.34 813.52,1810.07 793.13,1810.07
  Bottom Layer w15: v1(637.72,1607.27) 649.24,1618.79 746.13,1618.79 746.13,1688.92 v1(793.13,1735.92)
  Bottom Layer w20: v1(1149.61,351.68) 1149.61,607.21 v1(1151.24,608.84) 1459.88,608.84 1460.82,609.79 1460.82,643.71 J8.1@1483.3,666.19 ; v1(1928.59,2348.91) 1935.05,2355.36 J3.4@1935.05,2478.35
  other v3: 1315.83,1454.4
VIO2_IN: C35.1 J11.2 R102.2 R103.2 U1.15 | length 3259.5
  Top Layer w10: R102.2@569.59,1401.2 569.59,1401.99 592.74,1425.13 600.06,1425.13 v1@600.52,1425.59 ; R103.2@600.2,1397.11 600.52,1397.42 v1@600.52,1425.59 ; v1(600.83,1425.9) v1@600.52,1425.59
  Top Layer w20: v1(581.21,1852.47) 581.21,1729.7 593.19,1717.72 593.19,1642.44 v1(612.22,1623.41)
  L03_PWR w20: v1(581.21,1852.47) 578.48,1855.2 578.48,1893.55 590.2,1905.27 725.04,1905.27 728.73,1901.58 1089.7,1901.58 1093.39,1905.27 1667.26,1905.27 1710.84,1861.69 1710.84,1257.46 1429.19,975.82 v1(1384.96,975.82) ; J11.2@983.3,824.84 1098.81,940.35 v1(1147.64,940.35)
  Bottom Layer w10: v1(600.83,1425.9) 601.59,1426.66 605.13,1426.66 612.22,1433.76 v1(612.22,1623.41)
  Bottom Layer w20: v1(1147.64,940.35) 1220.9,1013.61 1347.17,1013.61 v1(1384.96,975.82)
  other v3: 1040.79,1276.04
XDS_5V: D1.2 FB1.2 U3.4 | length 1802.7
  Top Layer w6: 1752.76,57.01 1783.25,57.01 1785.48,59.23 FB1.2@1785.48,121.22
  Top Layer w10: 1800.63,84.21 1906.87,84.21 1960.73,138.08 U3.4@1969.67,138.08
  Top Layer w50: D1.2@627.89,311.85 695.49,311.85 v4(703.41,319.76) ; v4@1071.34,55.73 1105.91,55.73 1751.49,55.73
  Bottom Layer w50: 674.78,53.76 v4@1099.68,53.76 ; 696.99,55.91 672.67,55.91 643.38,85.2 643.38,271.24 v4(672.3,300.16) 691.9,319.76 v4(703.41,319.76)
  other v4: 1069.28,54.07 1105.91,55.2
XDS_RESET: C1.1 J7.10 J9.1 J22.10 R37.1 | length 4854.6
  Top Layer w6: v1(175.51,2246.16) 175.1,2246.57 175.1,2393.77 174.68,2394.18 176.25,2395.75 C1.1@176.25,2414.87 176.25,2469.55 180.28,2473.58 180.28,2478.87 196.99,2495.59 337.78,2495.59 345.79,2487.58 435.28,2487.58 435.5,2487.8 554.85,2487.8 578.01,2464.64 J9.1@707.96,2464.64 ; v1(591.06,114.86) 648.45,57.47 1011.1,57.47 1063.38,109.75 1096.6,109.75 J7.10@1102.5,115.64
  Bottom Layer w6: v1(175.51,2246.16) 175.18,2246.16 98.18,2169.15 98.18,1976.99 99.03,1976.14 99.03,569.74 74.86,545.58 74.86,97.23 74.98,97.12 74.98,89.32 75.46,89.8 201.49,89.8 212.98,101.28 577.48,101.28 v1(591.06,114.86) ; J7.10@1102.5,115.64 1158.41,171.56 1227.55,171.56 1264.13,208.14 1264.13,229.77 1350.53,316.17 1588.93,316.17 1671.59,398.83 1671.59,428.72 1668.08,432.24 J22.10@1615.87,432.24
